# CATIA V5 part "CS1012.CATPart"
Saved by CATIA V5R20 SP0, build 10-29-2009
Part number: CS1012
Revision: 4
Definition: design
Nomenclature: CS1012
Source: made
Description: NOT SPECIFIED
Bounding box of the stored display mesh (mm): x -11.818 to 12, y -12 to 12, z -22 to 6
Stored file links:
  C:\Users\Raffaele\Desktop\3D X SITO CF\BOLEX\20-TILTED COLUMN SUPPORT\CS1012.CATPart
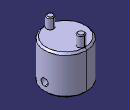
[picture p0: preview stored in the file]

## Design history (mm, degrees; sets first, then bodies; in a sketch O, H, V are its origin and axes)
Body1 "MANIFOLD_SOLID_BREP #683" (main body)
  Solid1: solid without history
